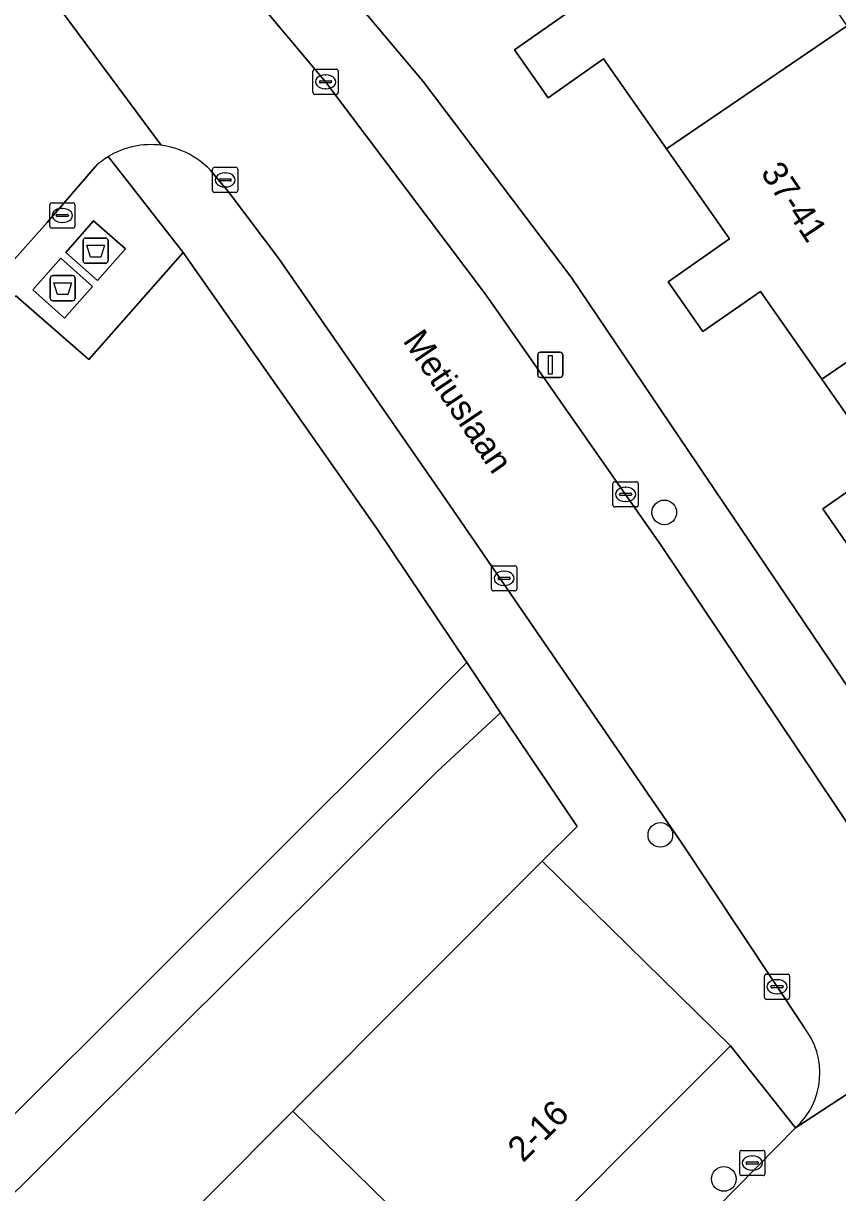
# Model space of a CAD drawing. Extents: x 159888 to 160761, y 384031 to 384750.
# Drawn here: x 160385.15 to 160417.48, y 384297.83 to 384344.25 of the extents above; entities that cross this region are included whole.
import ezdxf

# ---------------------------------------------------------------- set-up
doc = ezdxf.new("R2010")
doc.units = 0
for name, color, linetype in [('IMGEO_Afval_apart_plaats', 7, 'Continuous'), ('IMGEO_Boom', 7, 'Continuous'), ('IMGEO_Erf', 7, 'Continuous'), ('IMGEO_Groenvoorziening', 7, 'Continuous'), ('IMGEO_Kolk', 7, 'Continuous'), ('IMGEO_Lichtmast', 7, 'Continuous'), ('IMGEO_Openbare_ruimte_label', 7, 'Continuous'), ('IMGEO_Pand', 7, 'Continuous'), ('IMGEO_Pand_nummerreeks', 7, 'Continuous'), ('IMGEO_Rijbaan_lokaal_open', 7, 'Continuous'), ('IMGEO_Voetpad_gesloten', 7, 'Continuous'), ('IMGEO_Voetpad_halfverhard', 7, 'Continuous'), ('IMGEO_Voetpad_open', 7, 'Continuous')]:
    doc.layers.add(name, color=color, linetype=linetype)

msp = doc.modelspace()

# ---------------------------------------------------------------- linework, layer by layer
at = {"layer": 'IMGEO_Afval_apart_plaats'}
for p, q in [((160387.521, 384334.829), (160387.521, 384335.629)), ((160387.521, 384335.629), (160387.521, 384334.829)), ((160387.621, 384335.729), (160388.411, 384335.729)), ((160388.411, 384335.729), (160387.621, 384335.729)), ((160388.511, 384335.629), (160388.511, 384334.829)), ((160388.511, 384334.829), (160388.511, 384335.629)), ((160388.411, 384334.729), (160387.621, 384334.729)), ((160387.621, 384334.729), (160388.411, 384334.729)), ((160386.216, 384333.339), (160386.216, 384334.139)), ((160386.216, 384334.139), (160386.216, 384333.339)), ((160386.316, 384334.239), (160387.106, 384334.239)), ((160387.106, 384334.239), (160386.316, 384334.239)), ((160387.206, 384334.139), (160387.206, 384333.339)), ((160387.206, 384333.339), (160387.206, 384334.139)), ((160387.106, 384333.239), (160386.316, 384333.239)), ((160386.316, 384333.239), (160387.106, 384333.239))]:
    msp.add_line(p, q, dxfattribs=at)
for points in [[(160387.664, 384335.443), (160388.368, 384335.443), (160388.219, 384334.973), (160387.813, 384334.973), (160387.664, 384335.443)], [(160386.359, 384333.953), (160387.063, 384333.953), (160386.914, 384333.483), (160386.508, 384333.483), (160386.359, 384333.953)]]:
    msp.add_lwpolyline(points, dxfattribs=at)
for centre, start, end in [((160387.621, 384335.629), 90, 180), ((160387.621, 384335.629), 90, 180), ((160388.411, 384335.629), 0, 90), ((160388.411, 384335.629), 360, 90), ((160387.621, 384334.829), 180, 270), ((160387.621, 384334.829), 180, 270), ((160388.411, 384334.829), 270, 0), ((160388.411, 384334.829), 270, 0), ((160386.316, 384334.139), 90, 180), ((160386.316, 384334.139), 90, 180), ((160387.106, 384334.139), 0, 90), ((160387.106, 384334.139), 360, 90), ((160386.316, 384333.339), 180, 270), ((160386.316, 384333.339), 180, 270), ((160387.106, 384333.339), 270, 0), ((160387.106, 384333.339), 270, 0)]:
    msp.add_arc(centre, 0.1, start, end, dxfattribs=at)
at = {"layer": 'IMGEO_Boom'}
for centre in [(160410.598, 384324.838), (160410.441, 384312.035), (160412.962, 384298.376)]:
    msp.add_circle(centre, 0.489, dxfattribs=at)
at = {"layer": 'IMGEO_Erf'}
for points in [[(160354.597, 384397.082), (160401.024, 384341.943), (160406.906, 384334.176), (160430.378, 384299.406)], [(160418.299, 384322.96), (160416.889, 384324.975), (160419.284, 384326.651), (160416.848, 384330.131), (160414.413, 384333.61), (160412.132, 384332.013), (160410.75, 384333.987), (160413.186, 384335.692), (160410.686, 384339.264), (160408.186, 384342.836), (160405.986, 384341.297), (160404.655, 384343.2), (160406.806, 384344.705)]]:
    msp.add_lwpolyline(points, dxfattribs=at)
msp.add_lwpolyline([(160407.134, 384312.362), (160404.095, 384316.885), (160401.57, 384314.532), (160372.039, 384285.135), (160362.772, 384285.007), (160362.837, 384279.095), (160351.699, 384267.85), (160345.439, 384274.748), (160345.355, 384284.72), (160341.199, 384284.583), (160337.275, 384280.219), (160336.483, 384279.562), (160360.504, 384250.764), (160363.191, 384253.558), (160355.746, 384260.844), (160365.773, 384270.9), (160375.799, 384280.956), (160385.826, 384291.012), (160395.852, 384301.068), (160405.753, 384310.998)], close=True, dxfattribs=at)
at = {"layer": 'IMGEO_Groenvoorziening'}
msp.add_lwpolyline([(160362.609, 384308.421), (160362.749, 384287.577), (160371.557, 384287.736), (160402.753, 384318.884), (160399.209, 384324.159), (160391.497, 384335.159), (160387.746, 384330.904), (160384.849, 384333.43)], close=True, dxfattribs=at)
at = {"layer": 'IMGEO_Kolk'}
for p, q in [((160396.649, 384341.504), (160396.649, 384342.356)), ((160396.724, 384342.43), (160397.576, 384342.43)), ((160397.137, 384342.21), (160397.162, 384342.21)), ((160397.65, 384342.356), (160397.65, 384341.504)), ((160396.908, 384341.924), (160396.908, 384341.936)), ((160397.346, 384341.887), (160396.948, 384341.887)), ((160396.951, 384341.973), (160397.349, 384341.973)), ((160397.16, 384341.65), (160397.135, 384341.65)), ((160397.392, 384341.936), (160397.392, 384341.924)), ((160397.576, 384341.43), (160396.724, 384341.43)), ((160392.661, 384337.61), (160392.661, 384338.462)), ((160392.736, 384338.536), (160393.588, 384338.536)), ((160393.149, 384338.316), (160393.174, 384338.316)), ((160393.662, 384338.462), (160393.662, 384337.61)), ((160392.92, 384338.03), (160392.92, 384338.042)), ((160393.358, 384337.993), (160392.96, 384337.993)), ((160392.963, 384338.079), (160393.361, 384338.079)), ((160393.404, 384338.042), (160393.404, 384338.03)), ((160393.588, 384337.536), (160392.736, 384337.536)), ((160393.172, 384337.756), (160393.147, 384337.756)), ((160386.196, 384336.199), (160386.196, 384337.051)), ((160386.271, 384337.125), (160387.123, 384337.125)), ((160386.684, 384336.905), (160386.709, 384336.905)), ((160387.197, 384337.051), (160387.197, 384336.199)), ((160386.455, 384336.619), (160386.455, 384336.631)), ((160386.893, 384336.582), (160386.495, 384336.582)), ((160386.498, 384336.668), (160386.896, 384336.668)), ((160386.939, 384336.631), (160386.939, 384336.619)), ((160387.123, 384336.125), (160386.271, 384336.125)), ((160386.707, 384336.345), (160386.682, 384336.345)), ((160408.56, 384325.127), (160408.56, 384325.979)), ((160408.635, 384326.053), (160409.487, 384326.053)), ((160409.048, 384325.833), (160409.073, 384325.833)), ((160409.561, 384325.979), (160409.561, 384325.127)), ((160408.819, 384325.547), (160408.819, 384325.559)), ((160409.257, 384325.51), (160408.859, 384325.51)), ((160408.862, 384325.596), (160409.26, 384325.596)), ((160409.303, 384325.559), (160409.303, 384325.547)), ((160409.487, 384325.053), (160408.635, 384325.053)), ((160409.071, 384325.273), (160409.046, 384325.273)), ((160403.737, 384321.795), (160403.737, 384322.647)), ((160403.812, 384322.721), (160404.664, 384322.721)), ((160404.738, 384322.647), (160404.738, 384321.795)), ((160403.996, 384322.215), (160403.996, 384322.227)), ((160404.434, 384322.178), (160404.036, 384322.178)), ((160404.039, 384322.264), (160404.437, 384322.264)), ((160404.225, 384322.501), (160404.25, 384322.501)), ((160404.48, 384322.227), (160404.48, 384322.215)), ((160404.664, 384321.721), (160403.812, 384321.721)), ((160404.248, 384321.941), (160404.223, 384321.941)), ((160414.574, 384305.581), (160414.574, 384306.433)), ((160414.649, 384306.507), (160415.501, 384306.507)), ((160415.062, 384306.287), (160415.087, 384306.287)), ((160415.575, 384306.433), (160415.575, 384305.581)), ((160414.833, 384306.001), (160414.833, 384306.013)), ((160415.271, 384305.964), (160414.873, 384305.964)), ((160414.876, 384306.05), (160415.274, 384306.05)), ((160415.317, 384306.013), (160415.317, 384306.001)), ((160415.501, 384305.507), (160414.649, 384305.507)), ((160415.085, 384305.727), (160415.06, 384305.727)), ((160413.591, 384298.585), (160413.591, 384299.437)), ((160413.666, 384299.511), (160414.518, 384299.511)), ((160414.592, 384299.437), (160414.592, 384298.585)), ((160413.85, 384299.005), (160413.85, 384299.017)), ((160414.288, 384298.968), (160413.89, 384298.968)), ((160413.893, 384299.054), (160414.291, 384299.054)), ((160414.079, 384299.291), (160414.104, 384299.291)), ((160414.334, 384299.017), (160414.334, 384299.005)), ((160414.518, 384298.511), (160413.666, 384298.511)), ((160414.102, 384298.731), (160414.077, 384298.731))]:
    msp.add_line(p, q, dxfattribs=at)
for points in [[(160396.649, 384341.504), (160396.649, 384342.356)], [(160396.724, 384342.43), (160397.576, 384342.43)], [(160397.65, 384342.356), (160397.65, 384341.504)], [(160397.576, 384341.43), (160396.724, 384341.43)], [(160392.661, 384337.61), (160392.661, 384338.462)], [(160392.736, 384338.536), (160393.588, 384338.536)], [(160393.662, 384338.462), (160393.662, 384337.61)], [(160393.588, 384337.536), (160392.736, 384337.536)], [(160386.196, 384336.199), (160386.196, 384337.051)], [(160386.271, 384337.125), (160387.123, 384337.125)], [(160387.197, 384337.051), (160387.197, 384336.199)], [(160387.123, 384336.125), (160386.271, 384336.125)], [(160408.56, 384325.127), (160408.56, 384325.979)], [(160408.635, 384326.053), (160409.487, 384326.053)], [(160409.561, 384325.979), (160409.561, 384325.127)], [(160409.487, 384325.053), (160408.635, 384325.053)], [(160403.737, 384321.795), (160403.737, 384322.647)], [(160403.812, 384322.721), (160404.664, 384322.721)], [(160404.738, 384322.647), (160404.738, 384321.795)], [(160404.664, 384321.721), (160403.812, 384321.721)], [(160414.574, 384305.581), (160414.574, 384306.433)], [(160414.649, 384306.507), (160415.501, 384306.507)], [(160415.575, 384306.433), (160415.575, 384305.581)], [(160415.501, 384305.507), (160414.649, 384305.507)], [(160413.591, 384298.585), (160413.591, 384299.437)], [(160413.666, 384299.511), (160414.518, 384299.511)], [(160414.592, 384299.437), (160414.592, 384298.585)], [(160414.518, 384298.511), (160413.666, 384298.511)]]:
    msp.add_lwpolyline(points, dxfattribs=at)
for centre, radius, start, end in [((160396.726, 384342.354), 0.0765, 91.552, 178.448), ((160396.726, 384342.354), 0.0765, 91.552, 178.448), ((160397.574, 384342.354), 0.0765, 1.552, 88.448), ((160397.574, 384342.354), 0.0765, 1.552, 88.448), ((160396.948, 384341.933), 0.0403, 85.8775, 175.7526), ((160396.945, 384341.923), 0.0366, 178.938, 274.7102), ((160397.349, 384341.93), 0.043, 264.8664, 352.4533), ((160397.353, 384341.935), 0.0386, 1.7309, 96.639), ((160396.726, 384341.506), 0.0765, 181.552, 268.448), ((160396.726, 384341.506), 0.0765, 181.552, 268.448), ((160397.574, 384341.506), 0.0765, 271.552, 358.448), ((160397.574, 384341.506), 0.0765, 271.552, 358.448), ((160392.738, 384338.46), 0.0765, 91.552, 178.448), ((160392.738, 384338.46), 0.0765, 91.552, 178.448), ((160393.586, 384338.46), 0.0765, 1.552, 88.448), ((160393.586, 384338.46), 0.0765, 1.552, 88.448), ((160392.96, 384338.039), 0.0403, 85.8775, 175.7526), ((160392.957, 384338.029), 0.0366, 178.938, 274.7102), ((160393.361, 384338.036), 0.043, 264.8664, 352.4533), ((160393.365, 384338.041), 0.0386, 1.7309, 96.639), ((160392.738, 384337.612), 0.0765, 181.552, 268.448), ((160392.738, 384337.612), 0.0765, 181.552, 268.448), ((160393.586, 384337.612), 0.0765, 271.552, 358.448), ((160393.586, 384337.612), 0.0765, 271.552, 358.448), ((160386.273, 384337.049), 0.0765, 91.552, 178.448), ((160386.273, 384337.049), 0.0765, 91.552, 178.448), ((160387.121, 384337.049), 0.0765, 1.552, 88.448), ((160387.121, 384337.049), 0.0765, 1.552, 88.448), ((160386.495, 384336.628), 0.0403, 85.8775, 175.7526), ((160386.492, 384336.618), 0.0366, 178.938, 274.7102), ((160386.896, 384336.625), 0.043, 264.8664, 352.4533), ((160386.9, 384336.63), 0.0386, 1.7309, 96.639), ((160386.273, 384336.201), 0.0765, 181.552, 268.448), ((160386.273, 384336.201), 0.0765, 181.552, 268.448), ((160387.121, 384336.201), 0.0765, 271.552, 358.448), ((160387.121, 384336.201), 0.0765, 271.552, 358.448), ((160408.637, 384325.977), 0.0765, 91.552, 178.448), ((160408.637, 384325.977), 0.0765, 91.552, 178.448), ((160409.485, 384325.977), 0.0765, 1.552, 88.448), ((160409.485, 384325.977), 0.0765, 1.552, 88.448), ((160408.859, 384325.556), 0.0403, 85.8775, 175.7526), ((160408.856, 384325.546), 0.0366, 178.938, 274.7102), ((160409.26, 384325.553), 0.043, 264.8664, 352.4533), ((160409.264, 384325.558), 0.0386, 1.7309, 96.639), ((160408.637, 384325.129), 0.0765, 181.552, 268.448), ((160408.637, 384325.129), 0.0765, 181.552, 268.448), ((160409.485, 384325.129), 0.0765, 271.552, 358.448), ((160409.485, 384325.129), 0.0765, 271.552, 358.448), ((160403.814, 384322.645), 0.0765, 91.552, 178.448), ((160403.814, 384322.645), 0.0765, 91.552, 178.448), ((160404.662, 384322.645), 0.0765, 1.552, 88.448), ((160404.662, 384322.645), 0.0765, 1.552, 88.448), ((160404.036, 384322.224), 0.0403, 85.8775, 175.7526), ((160404.033, 384322.214), 0.0366, 178.938, 274.7102), ((160404.437, 384322.221), 0.043, 264.8664, 352.4533), ((160404.441, 384322.226), 0.0386, 1.7309, 96.639), ((160403.814, 384321.797), 0.0765, 181.552, 268.448), ((160403.814, 384321.797), 0.0765, 181.552, 268.448), ((160404.662, 384321.797), 0.0765, 271.552, 358.448), ((160404.662, 384321.797), 0.0765, 271.552, 358.448), ((160414.651, 384306.431), 0.0765, 91.552, 178.448), ((160414.651, 384306.431), 0.0765, 91.552, 178.448), ((160415.499, 384306.431), 0.0765, 1.552, 88.448), ((160415.499, 384306.431), 0.0765, 1.552, 88.448), ((160414.873, 384306.01), 0.0403, 85.8775, 175.7526), ((160414.87, 384306), 0.0366, 178.938, 274.7102), ((160415.274, 384306.007), 0.043, 264.8664, 352.4533), ((160415.278, 384306.012), 0.0386, 1.7309, 96.639), ((160414.651, 384305.583), 0.0765, 181.552, 268.448), ((160414.651, 384305.583), 0.0765, 181.552, 268.448), ((160415.499, 384305.583), 0.0765, 271.552, 358.448), ((160415.499, 384305.583), 0.0765, 271.552, 358.448), ((160413.668, 384299.435), 0.0765, 91.552, 178.448), ((160413.668, 384299.435), 0.0765, 91.552, 178.448), ((160414.516, 384299.435), 0.0765, 1.552, 88.448), ((160414.516, 384299.435), 0.0765, 1.552, 88.448), ((160413.89, 384299.014), 0.0403, 85.8775, 175.7526), ((160413.887, 384299.004), 0.0366, 178.938, 274.7102), ((160414.291, 384299.011), 0.043, 264.8664, 352.4533), ((160414.295, 384299.016), 0.0386, 1.7309, 96.639), ((160413.668, 384298.587), 0.0765, 181.552, 268.448), ((160413.668, 384298.587), 0.0765, 181.552, 268.448), ((160414.516, 384298.587), 0.0765, 271.552, 358.448), ((160414.516, 384298.587), 0.0765, 271.552, 358.448)]:
    msp.add_arc(centre, radius, start, end, dxfattribs=at)
for centre, major_axis, ratio, start_param, end_param in [((160397.136, 384341.93), (-0.387, 0.002), 0.722429, 4.712389, 7.853982), ((160397.161, 384341.93), (-0.39, 0.002), 0.717154, 1.570796, 4.712389), ((160393.148, 384338.036), (-0.387, 0.002), 0.722429, 4.712389, 7.853982), ((160393.173, 384338.036), (-0.39, 0.002), 0.717154, 1.570796, 4.712389), ((160386.683, 384336.625), (-0.387, 0.002), 0.722429, 4.712389, 7.853982), ((160386.708, 384336.625), (-0.39, 0.002), 0.717154, 1.570796, 4.712389), ((160409.047, 384325.553), (-0.387, 0.002), 0.722429, 4.712389, 7.853982), ((160409.072, 384325.553), (-0.39, 0.002), 0.717154, 1.570796, 4.712389), ((160404.224, 384322.221), (-0.387, 0.002), 0.722429, 4.712389, 7.853982), ((160404.249, 384322.221), (-0.39, 0.002), 0.717154, 1.570796, 4.712389), ((160415.061, 384306.007), (-0.387, 0.002), 0.722429, 4.712389, 7.853982), ((160415.086, 384306.007), (-0.39, 0.002), 0.717154, 1.570796, 4.712389), ((160414.078, 384299.011), (-0.387, 0.002), 0.722429, 4.712389, 7.853982), ((160414.103, 384299.011), (-0.39, 0.002), 0.717154, 1.570796, 4.712389)]:
    msp.add_ellipse(centre, major_axis=major_axis, ratio=ratio, start_param=start_param, end_param=end_param, dxfattribs=at)
at = {"layer": 'IMGEO_Lichtmast'}
for p, q in [((160405.574, 384330.296), (160405.574, 384331.096)), ((160405.574, 384331.096), (160405.574, 384330.296)), ((160405.674, 384331.196), (160406.464, 384331.196)), ((160406.464, 384331.196), (160405.674, 384331.196)), ((160406.564, 384331.096), (160406.564, 384330.296)), ((160406.564, 384330.296), (160406.564, 384331.096)), ((160406.464, 384330.196), (160405.674, 384330.196)), ((160405.674, 384330.196), (160406.464, 384330.196))]:
    msp.add_line(p, q, dxfattribs=at)
msp.add_lwpolyline([(160405.994, 384331.071), (160406.144, 384331.071), (160406.144, 384330.321), (160405.994, 384330.321), (160405.994, 384331.071)], dxfattribs=at)
for centre, start, end in [((160405.674, 384331.096), 90, 180), ((160405.674, 384331.096), 90, 180), ((160406.464, 384331.096), 0, 90), ((160406.464, 384331.096), 360, 90), ((160405.674, 384330.296), 180, 270), ((160405.674, 384330.296), 180, 270), ((160406.464, 384330.296), 270, 0), ((160406.464, 384330.296), 270, 0)]:
    msp.add_arc(centre, 0.1, start, end, dxfattribs=at)
at = {"layer": 'IMGEO_Pand'}
for points in [[(160410.218, 384353.473), (160403.961, 384348.051), (160406.806, 384344.705), (160404.655, 384343.2), (160405.986, 384341.297), (160408.186, 384342.836), (160410.686, 384339.264), (160417.858, 384344.151), (160416.114, 384346.711), (160414.22, 384349.165), (160414.474, 384349.34), (160412.898, 384351.271), (160412.714, 384351.115), (160412.453, 384350.894)], [(160417.858, 384344.151), (160410.686, 384339.264), (160413.186, 384335.692), (160410.75, 384333.987), (160412.132, 384332.013), (160414.413, 384333.61), (160416.848, 384330.131), (160424.065, 384335.047), (160422.25, 384337.711), (160420.864, 384339.742), (160421.35, 384340.074), (160420.01, 384342.04), (160419.523, 384341.708)], [(160424.065, 384335.047), (160416.848, 384330.131), (160419.284, 384326.651), (160416.889, 384324.975), (160418.299, 384322.96), (160420.578, 384324.555), (160423.041, 384321.035), (160430.211, 384325.919), (160428.415, 384328.556), (160427.008, 384330.622), (160427.148, 384330.715), (160427.49, 384330.945), (160426.096, 384332.99), (160425.666, 384332.697)], [(160395.852, 384301.068), (160403.325, 384293.755), (160413.221, 384303.667), (160405.753, 384310.998)], [(160393.291, 384283.706), (160403.325, 384293.755), (160395.852, 384301.068), (160385.826, 384291.012)]]:
    msp.add_lwpolyline(points, close=True, dxfattribs=at)
at = {"layer": 'IMGEO_Rijbaan_lokaal_open'}
for points in [[(160357.941, 384379.266), (160359.066, 384377.927), (160363.737, 384372.407), (160367.968, 384367.424), (160375.555, 384358.133), (160384.27, 384347.98), (160384.284, 384347.964), (160390.622, 384339.411)], [(160415.801, 384300.405), (160417.91, 384301.776), (160422.888, 384305.012), (160410.478, 384323.524), (160403.531, 384333.459), (160397.147, 384341.932), (160379.601, 384362.826)], [(160390.622, 384339.411), (160384.284, 384347.964)], [(160367.398, 384315.345), (160372.06, 384320.608), (160386.091, 384336.349), (160387.995, 384338.559)], [(160392.662, 384338.322), (160393.299, 384337.568), (160395.286, 384334.93), (160401.919, 384325.35), (160411.295, 384311.705), (160416.108, 384304.452), (160416.132, 384304.416)], [(160422.932, 384294.34), (160417.91, 384301.776), (160415.801, 384300.405), (160412.696, 384297.247), (160409.504, 384293.847), (160396.973, 384281.372), (160379.726, 384264.338), (160372.559, 384257.094), (160366.063, 384250.659), (160365.342, 384250), (160363.109, 384247.959), (160360.237, 384245.231), (160359.808, 384244.824), (160358.837, 384243.977), (160356.862, 384242.381), (160355.12, 384241.215), (160350.961, 384238.084), (160345.716, 384234.364), (160345.542, 384234.231)]]:
    msp.add_lwpolyline(points, dxfattribs=at)
for centre, radius, start, end in [((160390.213, 384336.199), 3.238, 82.7465, 121.5249), ((160390.217, 384336.197), 3.239, 40.9932, 82.8181), ((160390.138, 384336.291), 3.12, 121.2332, 133.3747), ((160413.852, 384302.585), 2.924, 311.8023, 38.7627)]:
    msp.add_arc(centre, radius, start, end, dxfattribs=at)
at = {"layer": 'IMGEO_Voetpad_gesloten'}
for points in [[(160389.2, 384335.297), (160387.936, 384336.412), (160386.832, 384335.161), (160388.096, 384334.046)], [(160387.896, 384333.81), (160386.637, 384334.924), (160385.526, 384333.668), (160386.785, 384332.554)]]:
    msp.add_lwpolyline(points, close=True, dxfattribs=at)
at = {"layer": 'IMGEO_Voetpad_halfverhard'}
msp.add_lwpolyline([(160401.57, 384314.532), (160404.095, 384316.885), (160402.753, 384318.884), (160371.557, 384287.736), (160362.749, 384287.577), (160362.609, 384308.421), (160360.161, 384305.668), (160360.319, 384287.543), (160343.576, 384287.226), (160341.199, 384284.583), (160345.355, 384284.72), (160362.772, 384285.007), (160372.039, 384285.135)], close=True, dxfattribs=at)
at = {"layer": 'IMGEO_Voetpad_open'}
for points in [[(160428.531, 384297.088), (160428.629, 384297.152), (160430.906, 384298.646), (160430.378, 384299.406), (160406.906, 384334.176), (160401.024, 384341.943), (160354.597, 384397.082)], [(160379.601, 384362.826), (160397.147, 384341.932), (160403.531, 384333.459), (160410.478, 384323.524), (160422.888, 384305.012)], [(160333.927, 384277.642), (160336.483, 384279.562), (160337.275, 384280.219), (160341.199, 384284.583), (160343.576, 384287.226), (160360.161, 384305.668), (160362.609, 384308.421), (160384.849, 384333.43), (160387.746, 384330.904), (160391.497, 384335.159), (160388.52, 384338.959)], [(160388.52, 384338.959), (160391.497, 384335.159), (160399.209, 384324.159), (160402.753, 384318.884), (160404.095, 384316.885), (160407.134, 384312.362), (160405.753, 384310.998), (160413.221, 384303.667), (160415.801, 384300.405)], [(160387.995, 384338.559), (160386.091, 384336.349), (160372.06, 384320.608), (160367.398, 384315.345), (160361.399, 384308.557), (160345.01, 384289.972), (160338.331, 384282.617), (160336.716, 384280.731), (160336.104, 384280.105), (160335.984, 384279.983), (160333.576, 384278.079), (160329.833, 384275.348), (160325.613, 384272.322), (160320.163, 384268.187), (160319.303, 384267.551), (160318.92, 384266.275), (160333.927, 384277.642)], [(160411.295, 384311.705), (160401.919, 384325.35), (160395.286, 384334.93), (160393.299, 384337.568), (160392.662, 384338.322)], [(160416.132, 384304.416), (160416.108, 384304.452), (160411.295, 384311.705)], [(160412.696, 384297.247), (160415.801, 384300.405), (160413.221, 384303.667), (160403.325, 384293.755), (160393.291, 384283.706), (160383.258, 384273.657), (160373.224, 384263.607), (160363.191, 384253.558), (160360.504, 384250.764), (160358.209, 384248.5), (160357.767, 384248.02), (160354.731, 384245.687), (160340.225, 384235.253), (160343.475, 384230.828), (160344.158, 384231.267)]]:
    msp.add_lwpolyline(points, dxfattribs=at)
for points in [[(160386.832, 384335.161), (160387.936, 384336.412), (160389.2, 384335.297), (160388.096, 384334.046)], [(160385.526, 384333.668), (160386.637, 384334.924), (160387.896, 384333.81), (160386.785, 384332.554)]]:
    msp.add_lwpolyline(points, close=True, dxfattribs=at)
for centre, radius, start, end in [((160390.213, 384336.199), 3.238, 82.7465, 121.5249), ((160390.217, 384336.197), 3.239, 40.9932, 82.8181), ((160390.138, 384336.291), 3.12, 121.2332, 133.3747), ((160413.852, 384302.585), 2.924, 311.8023, 38.7627)]:
    msp.add_arc(centre, radius, start, end, dxfattribs=at)

# ---------------------------------------------------------------- texts
at = {"layer": 'IMGEO_Openbare_ruimte_label'}
msp.add_text('Metiuslaan', height=1, rotation=304.0395, dxfattribs=at).set_placement((160400.192, 384331.652))
at = {"layer": 'IMGEO_Pand_nummerreeks'}
for s, rotation, p in [('37-41', 303.7642, (160414.399, 384338.321)), ('2-16', 45, (160404.988, 384298.995))]:
    msp.add_text(s, height=1, rotation=rotation, dxfattribs=at).set_placement(p)

doc.saveas('drawing.dxf')
